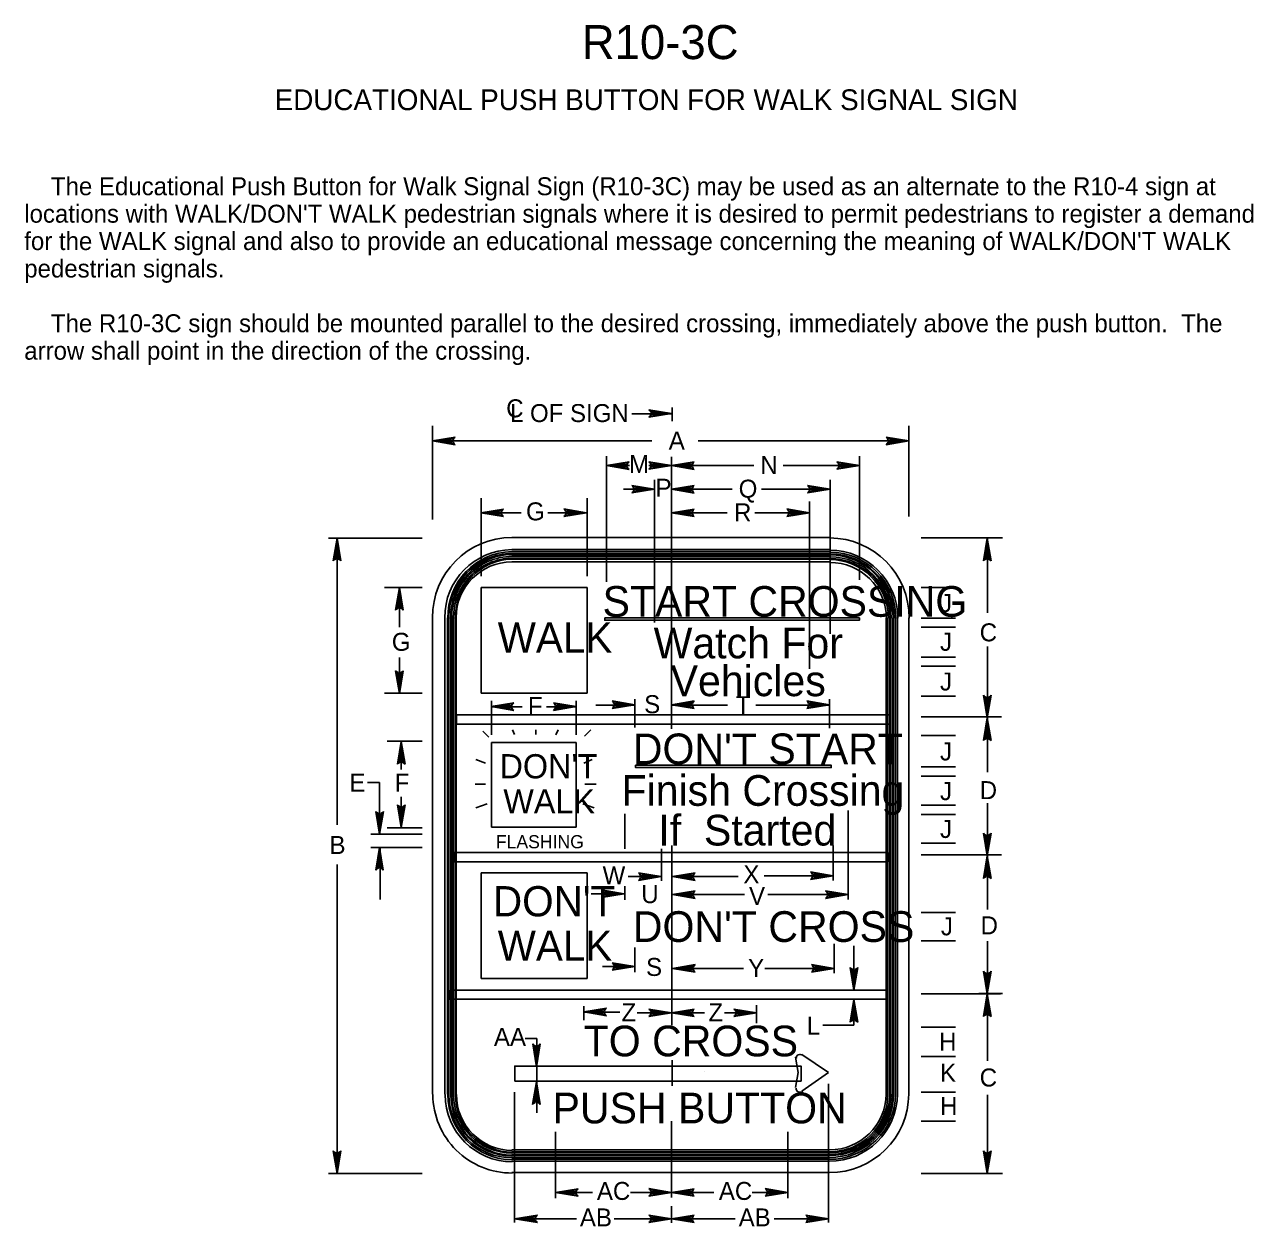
# Model space of a CAD drawing. Extents: x 0.013 to 0.196, y 0.004 to 0.259.
# Drawn here: x 0.0253 to 0.1878, y 0.1004 to 0.2593 of the extents above; entities that cross this region are included whole.
import ezdxf

# ---------------------------------------------------------------- set-up
doc = ezdxf.new("R2010")
doc.units = 0
for name, color, linetype in [('1', 7, 'Continuous'), ('12', 7, 'Continuous'), ('2', 7, 'Continuous'), ('3', 7, 'Continuous')]:
    doc.layers.add(name, color=color, linetype=linetype)

# ---------------------------------------------------------------- blocks, each defined once
blk = doc.blocks.new('RARROW')
at = {"layer": '3'}
for p, q in [((-2.156, 0.285), (-2.2665, 0.384625)), ((-2.2665, 0.384625), (0, 0)), ((0, 0), (-2.2665, -0.379125)), ((-2.156, 0.285), (-2.075625, 0.12075)), ((0, 0), (-2.156, 0.285)), ((-2.14975, -0.2705), (0, 0)), ((-2.075625, 0.12075), (0, 0)), ((0, 0), (-2.074, -0.108)), ((-2.2665, -0.379125), (-2.14975, -0.2705)), ((-2.074, -0.108), (-2.14975, -0.2705))]:
    blk.add_line(p, q, dxfattribs=at)

msp = doc.modelspace()

# ---------------------------------------------------------------- linework, layer by layer
at = {"layer": '1'}
for p, q in [((0.11093, 0.20783), (0.10561, 0.20783)), ((0.07925, 0.20625), (0.07925, 0.19387)), ((0.14225, 0.20625), (0.14225, 0.19425)), ((0.07925, 0.20425), (0.10825, 0.20425)), ((0.11438, 0.20425), (0.14225, 0.20425)), ((0.10225, 0.20225), (0.10225, 0.18563)), ((0.13575, 0.20225), (0.13575, 0.18588)), ((0.1053, 0.201), (0.10225, 0.201)), ((0.11088, 0.201), (0.10787, 0.201)), ((0.12175, 0.201), (0.11093, 0.201)), ((0.13575, 0.201), (0.12563, 0.201)), ((0.10862, 0.19912), (0.10862, 0.18025)), ((0.13187, 0.17875), (0.13187, 0.19912)), ((0.08569, 0.19668), (0.08569, 0.18639)), ((0.09969, 0.19668), (0.09969, 0.18639)), ((0.10862, 0.19787), (0.10453, 0.19787)), ((0.11093, 0.19787), (0.11888, 0.19787)), ((0.12275, 0.19787), (0.13187, 0.19787)), ((0.12912, 0.19625), (0.12912, 0.17413)), ((0.08569, 0.19475), (0.091, 0.19475)), ((0.09449, 0.19475), (0.09969, 0.19475)), ((0.11825, 0.19475), (0.11093, 0.19475)), ((0.12912, 0.19475), (0.12187, 0.19475)), ((0.0655, 0.19138), (0.07787, 0.19138)), ((0.06663, 0.1915), (0.06663, 0.1535)), ((0.15465, 0.19142), (0.14388, 0.19142)), ((0.15268, 0.19143), (0.15268, 0.18153)), ((0.07291, 0.18489), (0.07787, 0.18489)), ((0.07487, 0.18488), (0.07487, 0.17963)), ((0.14835, 0.18487), (0.14388, 0.18487)), ((0.14841, 0.1808), (0.14388, 0.1808)), ((0.14841, 0.17961), (0.14388, 0.17961)), ((0.07487, 0.17563), (0.07487, 0.17089)), ((0.14841, 0.17567), (0.14388, 0.17567)), ((0.15268, 0.17705), (0.15268, 0.16768)), ((0.14841, 0.17445), (0.14388, 0.17445)), ((0.07291, 0.17089), (0.07787, 0.17089)), ((0.08706, 0.16989), (0.08706, 0.16538)), ((0.08706, 0.1691), (0.09112, 0.1691)), ((0.09433, 0.1691), (0.09824, 0.1691)), ((0.09824, 0.16989), (0.09824, 0.16538)), ((0.10605, 0.16933), (0.10085, 0.16933)), ((0.106, 0.17012), (0.106, 0.16637)), ((0.11828, 0.16933), (0.11093, 0.16933)), ((0.1318, 0.16933), (0.12201, 0.16933)), ((0.13175, 0.17012), (0.13175, 0.16625)), ((0.14841, 0.17051), (0.14388, 0.17051)), ((0.14388, 0.16775), (0.1545, 0.16775)), ((0.15268, 0.16768), (0.15268, 0.16047)), ((0.08592, 0.16587), (0.0867, 0.16509)), ((0.09012, 0.16541), (0.08984, 0.16607)), ((0.09291, 0.16607), (0.09291, 0.16541)), ((0.09589, 0.16607), (0.09556, 0.1654)), ((0.10021, 0.16607), (0.09937, 0.16523)), ((0.07324, 0.16456), (0.07787, 0.16456)), ((0.07512, 0.1645), (0.07512, 0.16081)), ((0.14841, 0.16529), (0.14388, 0.16529)), ((0.085, 0.16212), (0.08625, 0.16162)), ((0.10038, 0.16212), (0.09925, 0.16162)), ((0.14841, 0.16116), (0.14388, 0.16116)), ((0.14841, 0.15991), (0.14388, 0.15991)), ((0.07066, 0.15908), (0.07225, 0.15908)), ((0.07225, 0.15908), (0.07225, 0.15225)), ((0.08488, 0.15888), (0.08625, 0.15888)), ((0.09938, 0.15888), (0.10088, 0.15888)), ((0.07512, 0.15718), (0.07512, 0.15313)), ((0.0865, 0.15625), (0.085, 0.15575)), ((0.09913, 0.15625), (0.10063, 0.15575)), ((0.14841, 0.1561), (0.14388, 0.1561)), ((0.15268, 0.15634), (0.15268, 0.14943)), ((0.10468, 0.15493), (0.10468, 0.15031)), ((0.13425, 0.15538), (0.13425, 0.14363)), ((0.14841, 0.15487), (0.14388, 0.15487)), ((0.07324, 0.15307), (0.07787, 0.15307)), ((0.07111, 0.15226), (0.07787, 0.15226)), ((0.07111, 0.15047), (0.07787, 0.15047)), ((0.07232, 0.15047), (0.07232, 0.14363)), ((0.10955, 0.15033), (0.10955, 0.14608)), ((0.13225, 0.15075), (0.13225, 0.14613)), ((0.14841, 0.15105), (0.14388, 0.15105)), ((0.06663, 0.14825), (0.06663, 0.1075)), ((0.14388, 0.1495), (0.1545, 0.1495)), ((0.15268, 0.14943), (0.15268, 0.1423)), ((0.10955, 0.14663), (0.10512, 0.14663)), ((0.11967, 0.14663), (0.11093, 0.14663)), ((0.13225, 0.14675), (0.12312, 0.14675)), ((0.10468, 0.14536), (0.10468, 0.14356)), ((0.10468, 0.14438), (0.10022, 0.14438)), ((0.1205, 0.14425), (0.11093, 0.14425)), ((0.13425, 0.14425), (0.12359, 0.14425)), ((0.14841, 0.14191), (0.14388, 0.14191)), ((0.106, 0.134), (0.106, 0.13725)), ((0.13237, 0.13775), (0.13237, 0.13387)), ((0.135, 0.13747), (0.135, 0.13161)), ((0.14841, 0.13815), (0.14388, 0.13815)), ((0.15268, 0.13808), (0.15268, 0.13118)), ((0.10175, 0.13475), (0.106, 0.13475)), ((0.11093, 0.1345), (0.12037, 0.1345)), ((0.12321, 0.1345), (0.13237, 0.1345)), ((0.135, 0.13041), (0.135, 0.12698)), ((0.14388, 0.13112), (0.15438, 0.13112)), ((0.15465, 0.13117), (0.15152, 0.13117)), ((0.15268, 0.13118), (0.15268, 0.12226)), ((0.09925, 0.1295), (0.09925, 0.12763)), ((0.0993, 0.1287), (0.10405, 0.1287)), ((0.10633, 0.12862), (0.11093, 0.12862)), ((0.11088, 0.12862), (0.11525, 0.12862)), ((0.11789, 0.12862), (0.12212, 0.12862)), ((0.12212, 0.12962), (0.12212, 0.12725)), ((0.135, 0.12698), (0.1309, 0.12698)), ((0.09152, 0.12522), (0.09305, 0.12522)), ((0.09305, 0.12522), (0.09305, 0.11538)), ((0.14841, 0.12673), (0.14388, 0.12673)), ((0.14841, 0.12285), (0.14388, 0.12285)), ((0.11525, 0.12087), (0.11525, 0.12087)), ((0.13162, 0.11925), (0.13162, 0.10088)), ((0.09012, 0.11813), (0.09012, 0.10088)), ((0.14841, 0.11811), (0.14388, 0.11811)), ((0.15268, 0.11778), (0.15268, 0.10737)), ((0.14841, 0.1143), (0.14388, 0.1143)), ((0.0955, 0.11288), (0.0955, 0.10412)), ((0.12625, 0.11288), (0.12625, 0.10412)), ((0.0655, 0.10737), (0.07787, 0.10737)), ((0.15465, 0.10737), (0.14388, 0.10737)), ((0.0955, 0.10487), (0.10043, 0.10487)), ((0.10546, 0.10487), (0.11088, 0.10487)), ((0.11088, 0.10487), (0.11646, 0.10487)), ((0.12155, 0.10487), (0.12625, 0.10487)), ((0.09012, 0.10138), (0.0983, 0.10138)), ((0.1033, 0.10138), (0.11088, 0.10138)), ((0.1193, 0.10138), (0.11088, 0.10138)), ((0.13162, 0.10138), (0.12443, 0.10138))]:
    msp.add_line(p, q, dxfattribs=at)
msp.add_ellipse((0.12789, 0.12266), major_axis=(-0.000518, 0), ratio=0.874034, start_param=4.011799, end_param=6.466875, dxfattribs=at)
at = {"layer": '12'}
for p, q in [((0.11097, 0.20689), (0.11097, 0.20868)), ((0.08975, 0.1915), (0.13175, 0.1915)), ((0.08975, 0.18988), (0.13175, 0.18988)), ((0.08975, 0.18963), (0.13175, 0.18963)), ((0.08975, 0.18938), (0.13175, 0.18938)), ((0.08975, 0.18925), (0.13175, 0.18925)), ((0.08975, 0.189), (0.13175, 0.189)), ((0.08975, 0.18875), (0.13175, 0.18875)), ((0.08975, 0.18863), (0.13175, 0.18863)), ((0.08975, 0.18825), (0.13175, 0.18825)), ((0.07925, 0.18088), (0.07925, 0.11788)), ((0.08088, 0.18088), (0.08088, 0.11788)), ((0.08125, 0.18088), (0.08125, 0.11788)), ((0.08138, 0.18088), (0.08138, 0.11788)), ((0.08163, 0.18088), (0.08163, 0.11788)), ((0.08175, 0.18088), (0.08175, 0.11788)), ((0.082, 0.18088), (0.082, 0.11788)), ((0.08225, 0.18088), (0.08225, 0.11788)), ((0.08238, 0.18088), (0.08238, 0.11788)), ((0.13925, 0.18088), (0.13925, 0.11788)), ((0.1395, 0.18088), (0.1395, 0.11788)), ((0.13975, 0.18088), (0.13975, 0.11788)), ((0.13987, 0.18088), (0.13987, 0.11788)), ((0.14012, 0.18088), (0.14012, 0.11788)), ((0.14025, 0.18088), (0.14025, 0.11788)), ((0.1405, 0.18088), (0.1405, 0.11788)), ((0.14075, 0.18088), (0.14075, 0.11788)), ((0.14225, 0.18088), (0.14225, 0.11788)), ((0.12763, 0.12075), (0.12725, 0.12275)), ((0.12812, 0.12312), (0.13162, 0.12075)), ((0.12725, 0.11875), (0.12763, 0.12075)), ((0.13162, 0.12075), (0.12812, 0.11825)), ((0.08975, 0.1105), (0.13175, 0.1105)), ((0.08975, 0.11025), (0.13175, 0.11025)), ((0.08975, 0.11013), (0.13175, 0.11013)), ((0.08975, 0.10988), (0.13175, 0.10988)), ((0.08975, 0.10975), (0.13175, 0.10975)), ((0.08975, 0.1095), (0.13175, 0.1095)), ((0.08975, 0.10925), (0.13175, 0.10925)), ((0.08975, 0.109), (0.13175, 0.109)), ((0.08975, 0.1075), (0.13175, 0.1075))]:
    msp.add_line(p, q, dxfattribs=at)
for points in [[(0.10203, 0.18085), (0.13573, 0.18085), (0.13573, 0.18053), (0.10203, 0.18053)], [(0.08243, 0.16801), (0.13983, 0.16801), (0.13983, 0.16681), (0.08243, 0.16681)], [(0.10611, 0.16137), (0.132, 0.16137), (0.132, 0.16105), (0.10611, 0.16105)], [(0.08213, 0.14981), (0.13953, 0.14981), (0.13953, 0.14861), (0.08213, 0.14861)], [(0.08153, 0.13161), (0.13925, 0.13161), (0.13925, 0.13042), (0.08153, 0.13042)], [(0.09014, 0.11959), (0.12801, 0.11959), (0.12801, 0.12159), (0.09014, 0.12159)]]:
    msp.add_lwpolyline(points, close=True, dxfattribs=at)
for centre, radius, start, end in [((0.08981, 0.18094), 0.01056, 90.339, 180.339), ((0.13174, 0.18087), 0.01056, 359.661, 89.661), ((0.08981, 0.18094), 0.00894, 90.4007, 180.4007), ((0.08993, 0.18099), 0.00864, 91.224, 181.224), ((0.08987, 0.18093), 0.00845, 90.8273, 180.8273), ((0.08993, 0.18099), 0.00826, 91.2795, 181.2795), ((0.08987, 0.18093), 0.00807, 90.8657, 180.8657), ((0.08987, 0.18093), 0.00782, 90.8934, 180.8934), ((0.08993, 0.18099), 0.00764, 91.3842, 181.3842), ((0.1318, 0.18081), 0.009, 0, 90), ((0.1318, 0.18081), 0.00875, 0, 90), ((0.1318, 0.18081), 0.0085, 0, 90), ((0.1318, 0.18081), 0.00838, 0, 90), ((0.1318, 0.18081), 0.00812, 0, 90), ((0.13186, 0.18074), 0.00794, 0.4511, 90.4511), ((0.1318, 0.18081), 0.00775, 0, 90), ((0.08975, 0.18088), 0.00737, 90, 180), ((0.13186, 0.18074), 0.00744, 0.4815, 90.4815), ((0.08974, 0.11787), 0.01044, 180.3431, 270.3431), ((0.0898, 0.11781), 0.00888, 180, 270), ((0.08986, 0.11774), 0.00856, 179.5818, 269.5818), ((0.0898, 0.11781), 0.00838, 180, 270), ((0.0898, 0.11781), 0.00813, 180, 270), ((0.0898, 0.11781), 0.008, 180, 270), ((0.0898, 0.11781), 0.00775, 180, 270), ((0.08986, 0.11774), 0.00756, 179.5265, 269.5265), ((0.0898, 0.11781), 0.00738, 180, 270), ((0.13181, 0.11794), 0.01044, 269.6569, 359.6569), ((0.13181, 0.11794), 0.00769, 269.5342, 359.5342), ((0.13187, 0.118), 0.00788, 269.0906, 359.0906), ((0.13181, 0.11794), 0.00894, 269.5993, 359.5993), ((0.13181, 0.11794), 0.00744, 269.5185, 359.5185), ((0.13181, 0.11794), 0.00806, 269.5559, 359.5559), ((0.13187, 0.118), 0.00825, 269.1319, 359.1319), ((0.13181, 0.11794), 0.00844, 269.5756, 359.5756), ((0.13181, 0.11794), 0.00869, 269.5878, 359.5878)]:
    msp.add_arc(centre, radius, start, end, dxfattribs=at)
for centre, start_param, end_param in [((0.12789, 0.12266), 4.011799, 6.466875), ((0.12789, 0.12266), 4.011799, 6.466875), ((0.12787, 0.11856), 6.078068, 8.589712)]:
    msp.add_ellipse(centre, major_axis=(-0.000518, 0), ratio=0.874034, start_param=start_param, end_param=end_param, dxfattribs=at)
at = {"layer": '3'}
for p, q in [((0.11088, 0.20215), (0.11088, 0.16617)), ((0.08569, 0.17089), (0.08569, 0.18489)), ((0.08569, 0.18489), (0.09969, 0.18489)), ((0.09969, 0.18489), (0.09969, 0.17089)), ((0.09969, 0.17089), (0.08569, 0.17089)), ((0.08704, 0.15318), (0.08704, 0.16438)), ((0.08704, 0.16438), (0.09824, 0.16438)), ((0.09824, 0.16438), (0.09824, 0.15318)), ((0.09824, 0.15318), (0.08704, 0.15318)), ((0.11093, 0.15076), (0.11093, 0.127)), ((0.08569, 0.13315), (0.08569, 0.14715)), ((0.08569, 0.14715), (0.09969, 0.14715)), ((0.09969, 0.14715), (0.09969, 0.13315)), ((0.09969, 0.13315), (0.08569, 0.13315)), ((0.11097, 0.12236), (0.11097, 0.11895)), ((0.11088, 0.11428), (0.11088, 0.10419)), ((0.11087, 0.10307), (0.11087, 0.10083))]:
    msp.add_line(p, q, dxfattribs=at)

# ---------------------------------------------------------------- block references
at = {"layer": '3', "xscale": 0.0013236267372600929, "yscale": 0.001309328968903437}
for p in [(0.11088, 0.20788), (0.14225, 0.20425), (0.11088, 0.201), (0.13575, 0.201), (0.10862, 0.19787), (0.13187, 0.19787), (0.09963, 0.19475), (0.12912, 0.19475), (0.09825, 0.16912), (0.106, 0.16937), (0.13175, 0.16937), (0.1095, 0.14663), (0.13225, 0.14675), (0.10462, 0.14438), (0.13425, 0.14425), (0.106, 0.13475), (0.13237, 0.1345), (0.11088, 0.12862), (0.12212, 0.12862), (0.11088, 0.10487), (0.12625, 0.10487), (0.11088, 0.10138), (0.13162, 0.10138)]:
    msp.add_blockref('RARROW', p, dxfattribs=at)
for p, rotation in [((0.07925, 0.20425), 180), ((0.10225, 0.201), 180), ((0.11088, 0.201), 180), ((0.11088, 0.19787), 180), ((0.08563, 0.19475), 180), ((0.11088, 0.19475), 180), ((0.06663, 0.19138), 90), ((0.15263, 0.19138), 90), ((0.07487, 0.18488), 90), ((0.07487, 0.17087), -90.00000000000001), ((0.087, 0.16912), 180), ((0.11088, 0.16937), 180), ((0.15263, 0.16762), -90.00000000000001), ((0.15263, 0.16762), 90), ((0.07512, 0.1645), 90), ((0.07512, 0.15313), -90.00000000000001), ((0.07225, 0.15225), -90.00000000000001), ((0.15263, 0.14938), -90.00000000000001), ((0.07225, 0.1505), 90), ((0.15263, 0.14938), 90), ((0.111, 0.14663), 180), ((0.111, 0.14425), 180), ((0.111, 0.1345), 180), ((0.135, 0.13162), -90.00000000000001), ((0.15263, 0.13112), -90.00000000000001), ((0.135, 0.13037), 90), ((0.15263, 0.13112), 90), ((0.09925, 0.12875), 180), ((0.11088, 0.12862), 180), ((0.093, 0.1215), -90.00000000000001), ((0.093, 0.1195), 90), ((0.06663, 0.10737), -90.00000000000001), ((0.15263, 0.10737), -90.00000000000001), ((0.0955, 0.10487), 180), ((0.11088, 0.10487), 180), ((0.09012, 0.10138), 180), ((0.11088, 0.10138), 180)]:
    msp.add_blockref('RARROW', p, dxfattribs=dict(at, rotation=rotation))

# ---------------------------------------------------------------- texts
at = {"layer": '1'}
for s, height, p in [('R10-3C', 0.0045, (0.099, 0.25475)), ('EDUCATIONAL PUSH BUTTON FOR WALK SIGNAL SIGN', 0.0027503, (0.05838, 0.248)), ('FLASHING', 0.001741, (0.08763, 0.15038))]:
    msp.add_text(s, height=height, dxfattribs=at).set_placement(p)
at = {"layer": '12'}
for s, height, p in [('START CROSSING', 0.0040575, (0.10175, 0.181)), ('WALK', 0.004, (0.08788, 0.17625)), ('Watch For', 0.00406, (0.1085, 0.1755)), ('Vehicles', 0.00406, (0.11075, 0.1705)), ("DON'T START", 0.0040605, (0.10575, 0.1615)), ("DON'T", 0.0032, (0.08812, 0.15963)), ('Finish Crossing', 0.0040605, (0.10425, 0.156)), ('WALK', 0.0032, (0.08862, 0.155)), ('If  Started', 0.0040605, (0.10912, 0.15075)), ("DON'T", 0.004, (0.08725, 0.14138)), ("DON'T CROSS", 0.0040605, (0.10575, 0.138)), ('WALK', 0.004, (0.08788, 0.1355)), ('TO CROSS', 0.00406, (0.09925, 0.12287)), ('PUSH BUTTON', 0.0040605, (0.09513, 0.114))]:
    msp.add_text(s, height=height, dxfattribs=at).set_placement(p)
at = {"layer": '2'}
for s, p in [('    The Educational Push Button for Walk Signal Sign (R10-3C) may be used as an alternate to the R10-4 sign at', (0.02525, 0.23675)), ("locations with WALK/DON'T WALK pedestrian signals where it is desired to permit pedestrians to register a demand", (0.02525, 0.23312)), ("for the WALK signal and also to provide an educational message concerning the meaning of WALK/DON'T WALK", (0.02525, 0.2295)), ('pedestrian signals.', (0.02525, 0.22587)), ('    The R10-3C sign should be mounted parallel to the desired crossing, immediately above the push button.  The', (0.02525, 0.21863)), ('arrow shall point in the direction of the crossing.', (0.02525, 0.215))]:
    msp.add_text(s, height=0.0023745, dxfattribs=at).set_placement(p)
at = {"layer": '3'}
for s, height, p in [('C', 0.00238, (0.089, 0.20738)), ('L OF SIGN', 0.002375, (0.0895, 0.20675)), ('A', 0.00238, (0.1105, 0.20312)), ('M', 0.00238, (0.10525, 0.2)), ('N', 0.00238, (0.12262, 0.19987)), ('P', 0.00238, (0.10875, 0.19687)), ('Q', 0.00238, (0.11975, 0.19675)), ('G', 0.00238, (0.09162, 0.19375)), ('R', 0.00238, (0.11913, 0.19362)), ('J', 0.00238, (0.14638, 0.18163)), ('G', 0.00238, (0.07387, 0.1765)), ('J', 0.00238, (0.14638, 0.1765)), ('C', 0.00238, (0.15163, 0.17775)), ('J', 0.00238, (0.14638, 0.17125)), ('F', 0.00238, (0.09187, 0.168)), ('S', 0.00238, (0.10725, 0.16825)), ('T', 0.00238, (0.11938, 0.16812)), ('J', 0.00238, (0.14638, 0.162)), ('E', 0.00238, (0.06825, 0.15788)), ('F', 0.00238, (0.07425, 0.15788)), ('J', 0.00238, (0.14638, 0.15675)), ('D', 0.00238, (0.15163, 0.15688)), ('J', 0.00238, (0.14638, 0.15175)), ('B', 0.00238, (0.06563, 0.14963)), ('W', 0.00238, (0.10175, 0.14563)), ('X', 0.00238, (0.12037, 0.14575)), ('U', 0.00238, (0.10687, 0.14313)), ('V', 0.00238, (0.12112, 0.14288)), ('J', 0.00238, (0.1465, 0.13887)), ('D', 0.00238, (0.15175, 0.139)), ('S', 0.00238, (0.1075, 0.1335)), ('Y', 0.00238, (0.121, 0.13337)), ('Z', 0.00238, (0.10425, 0.1275)), ('Z', 0.00238, (0.11575, 0.1275)), ('L', 0.00238, (0.12875, 0.12575)), ('AA', 0.002375, (0.08738, 0.12425)), ('H', 0.00238, (0.14625, 0.12362)), ('K', 0.00238, (0.14638, 0.1195)), ('C', 0.00238, (0.15163, 0.11888)), ('H', 0.00238, (0.14638, 0.11513)), ('AC', 0.002375, (0.101, 0.10388)), ('AC', 0.002375, (0.11713, 0.10388)), ('AB', 0.002375, (0.09875, 0.10038)), ('AB', 0.002375, (0.11975, 0.10038))]:
    msp.add_text(s, height=height, dxfattribs=at).set_placement(p)

doc.saveas('drawing.dxf')
